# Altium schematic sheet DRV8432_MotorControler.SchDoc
size B
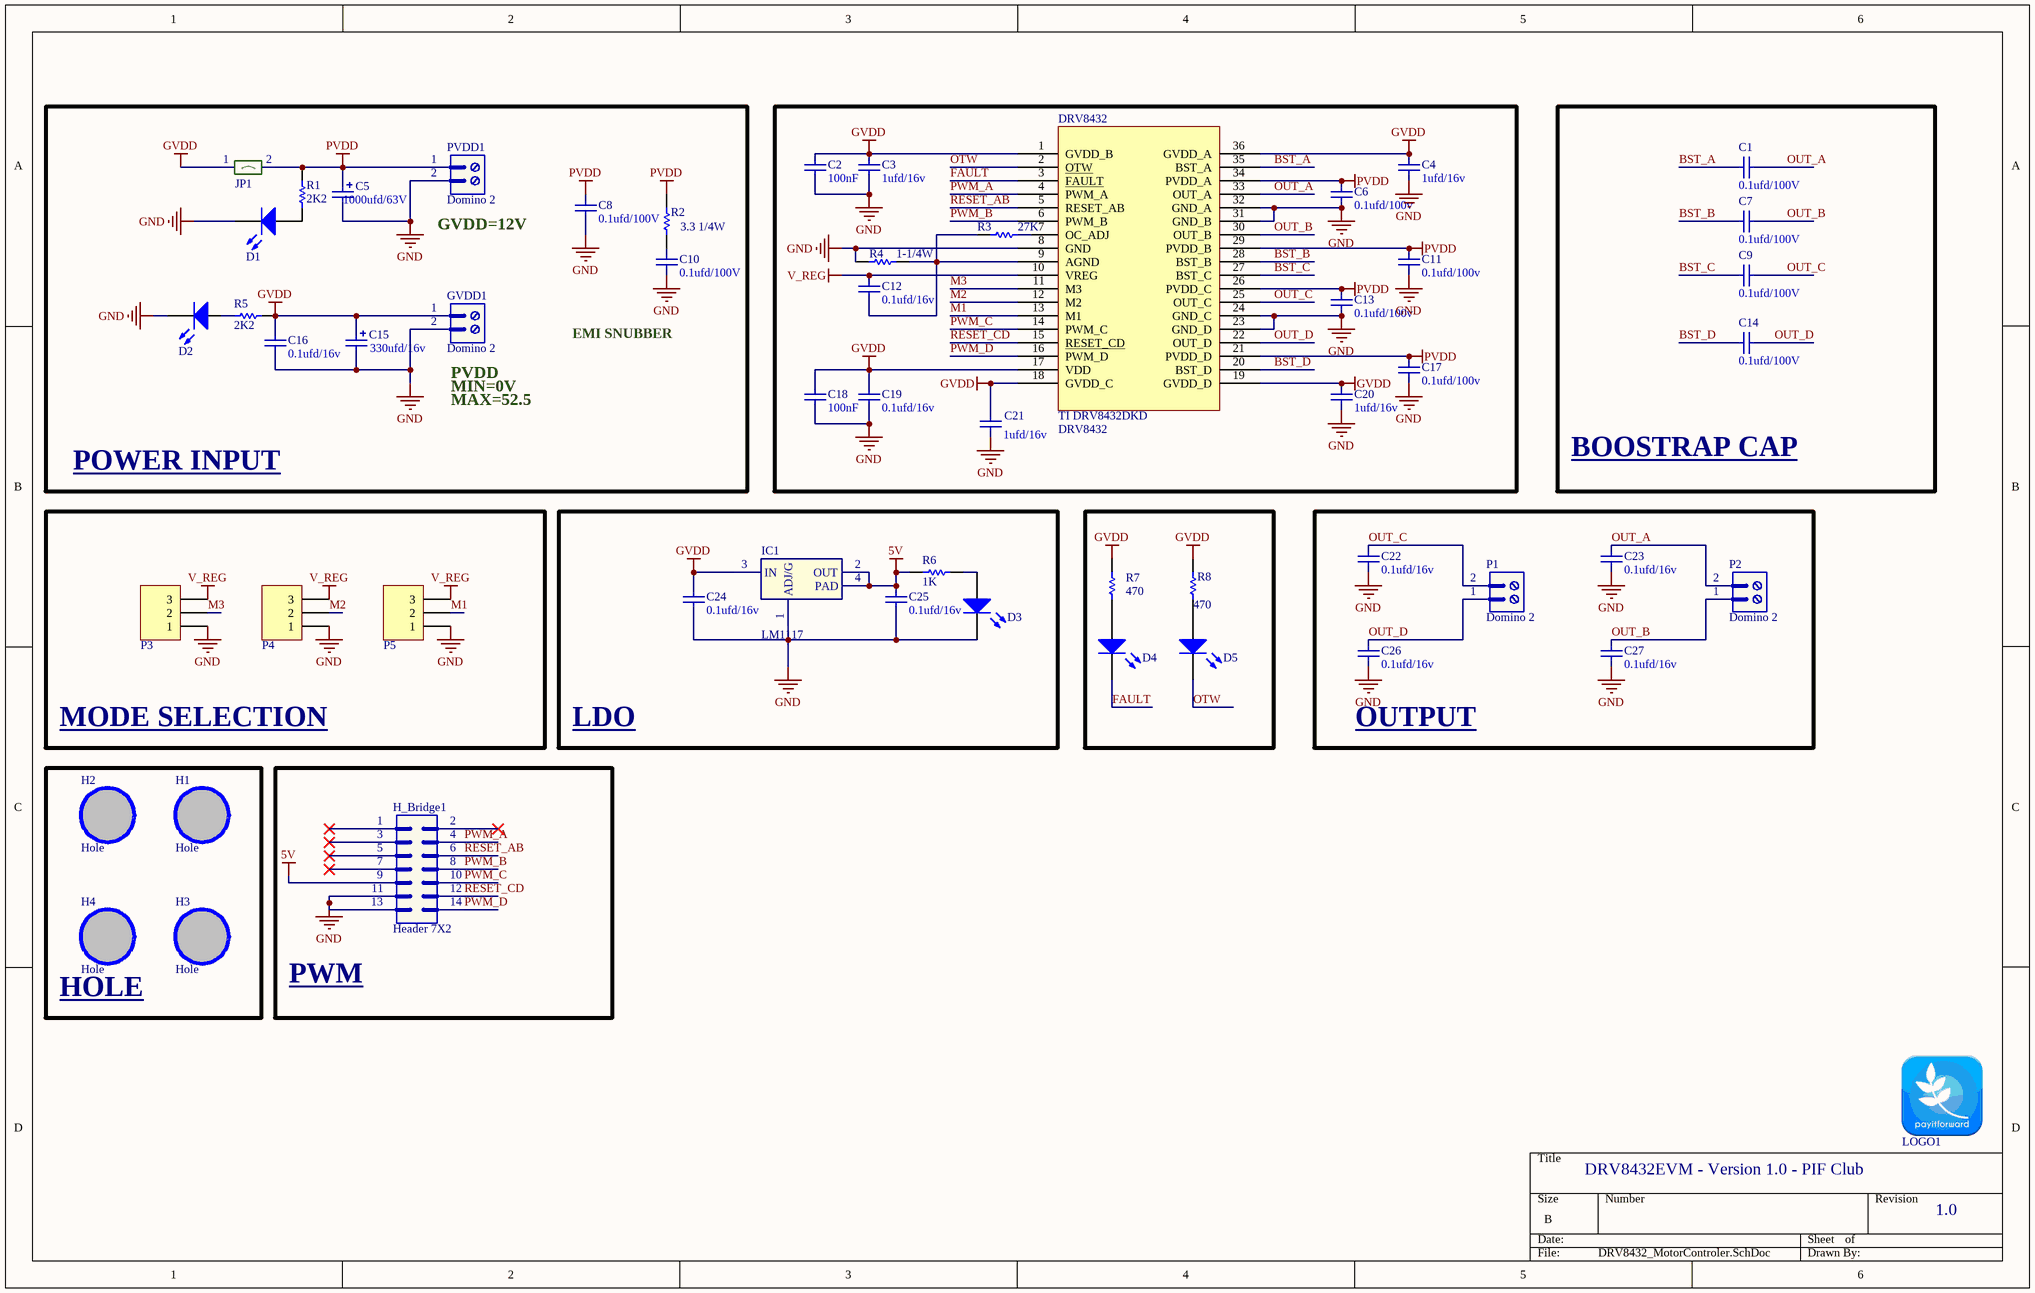
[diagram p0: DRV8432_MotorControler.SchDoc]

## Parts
C1  value 0.1ufd/100V  [CAP-SM-0805]  (hidden comment: Cap Non-Pol SMD)
C2  value 100nF  [CAP-SM-1210]  (hidden comment: Cap Non-Pol SMD)
C3  value 1ufd/16v  [CAP-SM-0603]  (hidden comment: Cap Non-Pol SMD)
C4  value 1ufd/16v  [CAP-SM-0603]  (hidden comment: Cap Non-Pol SMD)
C5  value 1000ufd/63V  [CP3/7]  (hidden comment: Cap Pol)
C6  value 0.1ufd/100v  [CAP-SM-0805]  (hidden comment: Cap Non-Pol SMD)
C7  value 0.1ufd/100V  [CAP-SM-0805]  (hidden comment: Cap Non-Pol SMD)
C8  value 0.1ufd/100V  [CAP-SM-0805]  (hidden comment: Cap Non-Pol SMD)
C9  value 0.1ufd/100V  [CAP-SM-0805]  (hidden comment: Cap Non-Pol SMD)
C10  value 0.1ufd/100V  [CAP-SM-0805]  (hidden comment: Cap Non-Pol SMD)
C11  value 0.1ufd/100v  [CAP-SM-0805]  (hidden comment: Cap Non-Pol SMD)
C12  value 0.1ufd/16v  [CAP-SM-0603]  (hidden comment: Cap Non-Pol SMD)
C13  value 0.1ufd/100v  [CAP-SM-0805]  (hidden comment: Cap Non-Pol SMD)
C14  value 0.1ufd/100V  [CAP-SM-0805]  (hidden comment: Cap Non-Pol SMD)
C15  value 330ufd/16v  [CP1/2.5]  (hidden comment: Cap Pol)
C16  value 0.1ufd/16v  [CAP-SM-0805]  (hidden comment: Cap Non-Pol SMD)
C17  value 0.1ufd/100v  [CAP-SM-0805]  (hidden comment: Cap Non-Pol SMD)
C18  value 100nF  [CAP-SM-1210]  (hidden comment: Cap Non-Pol SMD)
C19  value 0.1ufd/16v  [CAP-SM-0805]  (hidden comment: Cap Non-Pol SMD)
C20  value 1ufd/16v  [CAP-SM-0603]  (hidden comment: Cap Non-Pol SMD)
C21  value 1ufd/16v  [CAP-SM-0603]  (hidden comment: Cap Non-Pol SMD)
C22  value 0.1ufd/16v  [CAP-SM-0805]  (hidden comment: Cap Non-Pol SMD)
C23  value 0.1ufd/16v  [CAP-SM-0805]  (hidden comment: Cap Non-Pol SMD)
C24  value 0.1ufd/16v  [CAP-SM-0805]  (hidden comment: Cap Non-Pol SMD)
C25  value 0.1ufd/16v  [CAP-SM-0805]  (hidden comment: Cap Non-Pol SMD)
C26  value 0.1ufd/16v  [CAP-SM-0805]  (hidden comment: Cap Non-Pol SMD)
C27  value 0.1ufd/16v  [CAP-SM-0805]  (hidden comment: Cap Non-Pol SMD)
D1  LED SMD  [LED_0603_Blue]  (value not drawn)
D2  LED SMD  [LED_0603_Blue]  (value not drawn)
D3  LED SMD  [LED_0603_Blue]  (value not drawn)
D4  LED SMD  [LED_0603_Blue]  (value not drawn)
D5  LED SMD  [LED_0603_Blue]  (value not drawn)
DRV8432  DRV8432  [PCBComponent_1]
GVDD1  Domino 2  [DOMINO 2- 5mm]
H1  Hole  [LO KHOAN 3MM]
H2  Hole  [LO KHOAN 3MM]
H3  Hole  [LO KHOAN 3MM]
H4  Hole  [LO KHOAN 3MM]
H_Bridge1  Header 7X2  [JP7X2]
IC1  LM1117  [SOT223-4N]
JP1  Jumper 2  [JP2]  (value not drawn)
LOGO1  LOGO PIF  [PIF LOGO TOP OVERLAY]  (value not drawn)
P1  Domino 2  [DOMINO 2- 5mm]
P2  Domino 2  [DOMINO 2- 5mm]
P3  Header 3  [JP3]  (value not drawn)
P4  Header 3  [JP3]  (value not drawn)
P5  Header 3  [JP3]  (value not drawn)
PVDD1  Domino 2  [DOMINO 2- 5mm]
R1  value 2K2  [RES-SM-0603]  (hidden comment: RESISTOR SMD)
R2  value 3.3 1/4W  [RES-SM-1206]  (hidden comment: RESISTOR SMD)
R3  value 27K  [RES-SM-0603]  (hidden comment: RESISTOR SMD)
R4  value 1-1/4W  [RES-SM-0805]  (hidden comment: RESISTOR SMD)
R5  value 2K2  [RES-SM-0603]  (hidden comment: RESISTOR SMD)
R6  value 1K  [RES-SM-0603]  (hidden comment: RESISTOR SMD)
R7  value 470  [RES-SM-0603]  (hidden comment: RESISTOR SMD)
R8  value 470  [RES-SM-0603]  (hidden comment: RESISTOR SMD)

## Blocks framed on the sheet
POWER INPUT: C5 C8 C10 C15 C16 D1 D2 GVDD1 JP1 PVDD1 R1 R2 R5
BOOSTRAP CAP: C1 C7 C9 C14
MODE SELECTION: P3-P5
LDO: C24 C25 D3 IC1 R6
OUTPUT: C22 C23 C26 C27 P1 P2
HOLE: H1-H4
PWM: H_Bridge1

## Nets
5V: C25.2 H_Bridge1.9 IC1.2(OUT) IC1.4(PAD) R6.2
GND: C2.1 C3.2 C4.2 C5.2 C6.1 C8.1 C10.1 C11.1 C13.1 C15.2 C16.1 C17.1 C18.1 C19.1 C20.1 C21.1 C22.1 C23.1 C24.1 C25.1 C26.1 C27.1 D1.2(K) D2.2(K) D3.2(K) DRV8432.8(GND) DRV8432.23(GND_D) DRV8432.24(GND_C) DRV8432.31(GND_B) DRV8432.32(GND_A) GVDD1.2 H_Bridge1.11 H_Bridge1.13 IC1.1(ADJ/G) P3.1 P4.1 P5.1 PVDD1.2 R4.2
GVDD: C2.2 C3.1 C4.1 C15.1 C16.2 C18.2 C19.2 C20.2 C21.2 C24.2 DRV8432.1(GVDD_B) DRV8432.17(VDD) DRV8432.18(GVDD_C) DRV8432.19(GVDD_D) DRV8432.36(GVDD_A) GVDD1.1 IC1.3(IN) JP1.1 R5.2 R7.2 R8.2
PVDD: C5.1 C6.2 C8.2 C11.2 C13.2 C17.2 DRV8432.21(PVDD_D) DRV8432.26(PVDD_C) DRV8432.29(PVDD_B) DRV8432.34(PVDD_A) JP1.2 PVDD1.1 R1.2 R2.2
V_REG: C12.1 DRV8432.10(VREG) P3.3 P4.3 P5.3
BST_A: C1.1 DRV8432.35(BST_A)
BST_B: C7.1 DRV8432.28(BST_B)
BST_C: C9.1 DRV8432.27(BST_C)
BST_D: C14.1 DRV8432.20(BST_D)
FAULT: D4.2(K) DRV8432.3(FAULT)
M1: DRV8432.13(M1) P5.2
M2: DRV8432.12(M2) P4.2
M3: DRV8432.11(M3) P3.2
OTW: D5.2(K) DRV8432.2(OTW)
OUT_A: C1.2 C23.2 DRV8432.33(OUT_A) P2.2
OUT_B: C7.2 C27.2 DRV8432.30(OUT_B) P2.1
OUT_C: C9.2 C22.2 DRV8432.25(OUT_C) P1.2
OUT_D: C14.2 C26.2 DRV8432.22(OUT_D) P1.1
PWM_A: DRV8432.4(PWM_A) H_Bridge1.4
PWM_B: DRV8432.6(PWM_B) H_Bridge1.8
PWM_C: DRV8432.14(PWM_C) H_Bridge1.10
PWM_D: DRV8432.16(PWM_D) H_Bridge1.14
RESET_AB: DRV8432.5(RESET_AB) H_Bridge1.6
RESET_CD: DRV8432.15(RESET_CD) H_Bridge1.12
NetC10_2: C10.2 R2.1
NetC12_2: C12.2 DRV8432.9(AGND) R3.2 R4.1
NetD1_1: D1.1(A) R1.1
NetD2_1: D2.1(A) R5.1
NetD3_1: D3.1(A) R6.1
NetD4_1: D4.1(A) R7.1
NetD5_1: D5.1(A) R8.1
NetDRV8432_7: DRV8432.7(OC_ADJ) R3.1

Not connected (* = marked no-connect by the designer): H1 1; H2 1; H3 1; H4 1; H_Bridge1 1* 2* 3* 5* 7*

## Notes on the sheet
- (near PVDD1) GVDD=12V
- EMI SNUBBER
- (near GVDD1) PVDD
- (near GVDD1) MIN=0V
- MAX=52.5
- (near LOGO1) DRV8432EVM - Version 1.0 - PIF Club
- 1.0

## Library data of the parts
C1-C4 C6-C14 C16-C27 = Cap Non-Pol SMD: Capacitor
C5 C15 = Cap Pol: Polarized Capacitor (Radial)
D1-D5 = LED SMD: LED
DRV8432 = Component_1
GVDD1 P1 P2 PVDD1 = Domino 2: Domino, 2-Pin
H1-H4 = Hole: Hole 3mm
H_Bridge1 = Header 7X2: Header, 7-Pin, Dual row
IC1 = LM1117: Available in 1.8V, 2.5V, 2.85V, 3.3V, 5V, and  Adjustable Versions; Value: LM317
P3-P5 = Header 3: Header, 3-Pin
R1-R8 = RESISTOR SMD: Resistor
